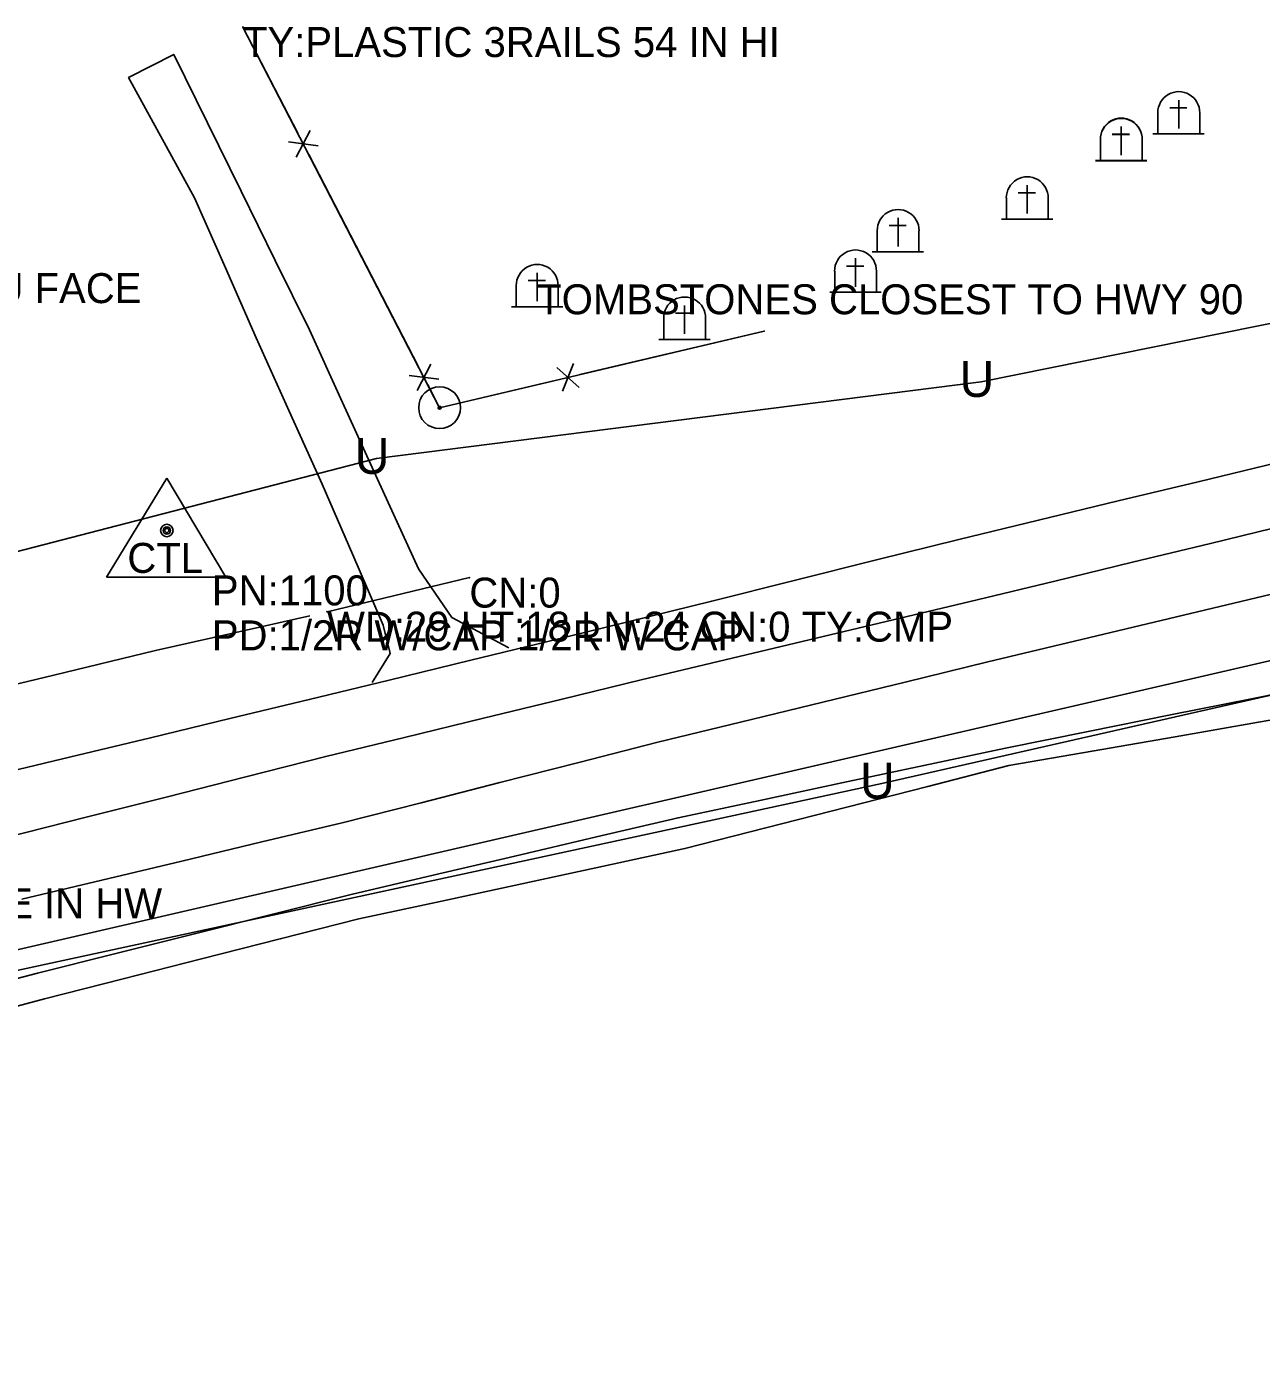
# Model space of a CAD drawing. Extents: x 1568433 to 1572450, y 731863 to 733450.
# Drawn here: x 1569410.1 to 1569616, y 731973.5 to 732195.3 of the extents above; entities that cross this region are included whole.
import ezdxf

# ---------------------------------------------------------------- set-up
doc = ezdxf.new("R2010")
doc.units = 0
for name, color, linetype in [('Default', 7, 'Continuous'), ('S_BASELINE', 7, 'Continuous'), ('S_BUILDING_ANNOT', 7, 'Continuous'), ('S_CROSS_DRAIN', 7, 'Continuous'), ('S_CROSS_DRAIN_ANNOT', 7, 'Continuous'), ('S_DITCHLINE', 7, 'Continuous'), ('S_DRG_PT_SYM', 7, 'Continuous'), ('S_DRIVEWAY', 7, 'Continuous'), ('S_EDGE_PAVEMENT', 7, 'Continuous'), ('S_FENCE', 7, 'Continuous'), ('S_FENCE_ANNOT', 7, 'Continuous'), ('S_MSC_PT_SYM', 7, 'Continuous'), ('S_PAVEMENT_CROWN', 7, 'Continuous'), ('S_PRIMARY_CTL', 7, 'Continuous'), ('S_PRIMARY_CTL_ANNOT', 7, 'Continuous'), ('S_TOMBSTONE', 7, 'Continuous'), ('S_TOMBSTONE_ANNOT', 7, 'Continuous'), ('S_UNDERGROUND_CABLE', 7, 'Continuous')]:
    doc.layers.add(name, color=color, linetype=linetype)

msp = doc.modelspace()

# ---------------------------------------------------------------- linework, layer by layer
at = {"layer": 'S_BASELINE'}
msp.add_line((1569114.63, 731973.54), (1569838.9, 732140.65), dxfattribs=at)
at = {"layer": 'S_CROSS_DRAIN'}
msp.add_line((1569460.2, 732097.74), (1569483.93, 732103.42), dxfattribs=at)
at = {"layer": 'S_DITCHLINE'}
for points in [[(1569330.52, 732066.86), (1569334.31, 732068.88), (1569357.83, 732073.3), (1569377.75, 732078.21), (1569397.67, 732083.12), (1569414.63, 732087.18), (1569431.6, 732091.25), (1569444.47, 732094.14), (1569457.35, 732097.03)], [(1569399.35, 732034.15), (1569411.9, 732037.47), (1569424.99, 732040.75), (1569438.07, 732044.04), (1569451.15, 732047.32), (1569464.24, 732050.6), (1569477.87, 732053.79), (1569491.49, 732056.99), (1569505.12, 732060.18), (1569518.75, 732063.37), (1569532.4, 732066.27), (1569546.05, 732069.17), (1569559.71, 732072.07), (1569573.36, 732074.96), (1569587.12, 732077.74), (1569600.88, 732080.51), (1569614.65, 732083.28), (1569628.41, 732086.06)], [(1569400.55, 732029.85), (1569413.06, 732033.17), (1569426.17, 732036.5), (1569439.27, 732039.83), (1569452.38, 732043.16), (1569465.48, 732046.49), (1569479.08, 732049.42), (1569492.68, 732052.35), (1569506.28, 732055.29), (1569519.87, 732058.22), (1569533.38, 732061.68), (1569546.89, 732065.14), (1569560.4, 732068.6), (1569573.91, 732072.06), (1569587.79, 732074.48), (1569601.67, 732076.89), (1569615.54, 732079.3), (1569629.42, 732081.72)]]:
    msp.add_lwpolyline(points, dxfattribs=at)
at = {"layer": 'S_DRG_PT_SYM'}
for points in [[(1569483.93, 732103.42), (1569483.93, 732103.47), (1569483.93, 732103.42), (1569483.88, 732103.42), (1569483.93, 732103.42), (1569483.93, 732103.37), (1569483.93, 732103.42), (1569483.98, 732103.42)], [(1569460.2, 732097.74), (1569460.2, 732097.79), (1569460.2, 732097.74), (1569460.15, 732097.74), (1569460.2, 732097.74), (1569460.2, 732097.69), (1569460.2, 732097.74), (1569460.25, 732097.74)]]:
    msp.add_lwpolyline(points, dxfattribs=at)
at = {"layer": 'S_DRIVEWAY'}
msp.add_lwpolyline([(1569467.73, 732085.91), (1569470.71, 732090.77), (1569469.58, 732095.49), (1569464.48, 732107.23), (1569459.38, 732118.98), (1569453.89, 732131.19), (1569448.4, 732143.4), (1569443.25, 732155.08), (1569438.1, 732166.76), (1569427.09, 732186.8), (1569434.63, 732190.68), (1569440.24, 732179.28), (1569445.85, 732167.88), (1569451.55, 732156.3), (1569457.25, 732144.72), (1569462.49, 732133.26), (1569467.72, 732121.8), (1569475.43, 732104.88), (1569481.03, 732096.75), (1569490.49, 732091.72)], dxfattribs=at)
at = {"layer": 'S_EDGE_PAVEMENT'}
for points in [[(1569404.23, 732070.38), (1569417.48, 732073.55), (1569430.73, 732076.72), (1569443.98, 732079.9), (1569457.24, 732083.07), (1569470.58, 732086.32), (1569483.93, 732089.58), (1569497.27, 732092.83), (1569510.61, 732096.08), (1569524.35, 732099.51), (1569538.09, 732102.93), (1569551.83, 732106.36), (1569565.57, 732109.79), (1569578.87, 732112.99), (1569592.17, 732116.2), (1569605.47, 732119.41), (1569618.77, 732122.62)], [(1569409.29, 732049.82), (1569422.64, 732052.99), (1569435.99, 732056.16), (1569449.34, 732059.34), (1569462.7, 732062.51), (1569475.87, 732065.88), (1569489.04, 732069.24), (1569502.21, 732072.61), (1569515.38, 732075.97), (1569529.13, 732079.31), (1569542.88, 732082.66), (1569556.63, 732086.01), (1569570.38, 732089.35), (1569583.67, 732092.52), (1569596.96, 732095.69), (1569610.25, 732098.87), (1569623.54, 732102.04)]]:
    msp.add_lwpolyline(points, dxfattribs=at)
at = {"layer": 'S_FENCE'}
for p, q in [((1569446.17, 732195.24), (1569478.97, 732131.76)), ((1569453.76, 732176.1), (1569458.71, 732175.44)), ((1569453.76, 732176.1), (1569458.71, 732175.44)), ((1569457.4, 732177.98), (1569455.07, 732173.56)), ((1569457.4, 732177.98), (1569455.07, 732173.56)), ((1569478.97, 732131.76), (1569533.09, 732144.52)), ((1569477.53, 732139.03), (1569475.2, 732134.61)), ((1569477.53, 732139.03), (1569475.2, 732134.61)), ((1569498.52, 732138.47), (1569502.25, 732135.14)), ((1569498.52, 732138.47), (1569502.25, 732135.14)), ((1569499.46, 732134.49), (1569501.31, 732139.13)), ((1569499.46, 732134.49), (1569501.31, 732139.13)), ((1569473.89, 732137.15), (1569478.84, 732136.49)), ((1569473.89, 732137.15), (1569478.84, 732136.49))]:
    msp.add_line(p, q, dxfattribs=at)
for points in [[(1569446.17, 732195.24), (1569455.32, 732177.54)], [(1569446.17, 732195.24), (1569455.32, 732177.54)], [(1569457.15, 732174), (1569475.45, 732138.59)], [(1569457.15, 732174), (1569475.45, 732138.59)], [(1569502.33, 732137.27), (1569533.09, 732144.52)], [(1569502.33, 732137.27), (1569533.09, 732144.52)], [(1569478.97, 732131.76), (1569498.44, 732136.35)], [(1569478.97, 732131.76), (1569498.44, 732136.35)], [(1569477.02, 732135.55), (1569478.97, 732131.76)], [(1569477.02, 732135.55), (1569478.97, 732131.76)]]:
    msp.add_lwpolyline(points, dxfattribs=at)
for radius in [3.49, 0.247, 0.0349]:
    msp.add_circle((1569478.97, 732131.76), radius, dxfattribs=at)
at = {"layer": 'S_MSC_PT_SYM'}
for points in [[(1569446.17, 732195.24), (1569446.17, 732195.29), (1569446.17, 732195.24), (1569446.12, 732195.24), (1569446.17, 732195.24), (1569446.17, 732195.19), (1569446.17, 732195.24), (1569446.22, 732195.24)], [(1569533.09, 732144.52), (1569533.09, 732144.57), (1569533.09, 732144.52), (1569533.04, 732144.52), (1569533.09, 732144.52), (1569533.09, 732144.47), (1569533.09, 732144.52), (1569533.14, 732144.52)], [(1569478.97, 732131.76), (1569478.97, 732131.81), (1569478.97, 732131.76), (1569478.92, 732131.76), (1569478.97, 732131.76), (1569478.97, 732131.71), (1569478.97, 732131.76), (1569479.02, 732131.76)]]:
    msp.add_lwpolyline(points, dxfattribs=at)
at = {"layer": 'S_PAVEMENT_CROWN'}
msp.add_lwpolyline([(1569406.7, 732060.07), (1569420.02, 732063.45), (1569433.34, 732066.83), (1569446.66, 732070.21), (1569459.98, 732073.59), (1569473.13, 732076.78), (1569486.27, 732079.97), (1569499.41, 732083.16), (1569512.56, 732086.35), (1569526.57, 732089.69), (1569540.59, 732093.02), (1569554.6, 732096.36), (1569568.61, 732099.7), (1569581.58, 732102.84), (1569594.55, 732105.98), (1569607.52, 732109.12), (1569620.49, 732112.26)], dxfattribs=at)
at = {"layer": 'S_PRIMARY_CTL'}
for p, q in [((1569433.48, 732119.99), (1569423.44, 732103.47)), ((1569433.48, 732119.99), (1569423.44, 732103.47)), ((1569433.48, 732119.99), (1569443.3, 732103.47)), ((1569433.48, 732119.99), (1569443.3, 732103.47)), ((1569423.44, 732103.47), (1569443.3, 732103.47)), ((1569423.44, 732103.47), (1569443.3, 732103.47))]:
    msp.add_line(p, q, dxfattribs=at)
for radius in [1.04, 1.04, 0.609, 0.609, 0.344, 0.344]:
    msp.add_circle((1569433.48, 732111.29), radius, dxfattribs=at)
at = {"layer": 'S_TOMBSTONE'}
for p, q in [((1569602.25, 732183.07), (1569602.25, 732178.34)), ((1569598.76, 732180.94), (1569598.76, 732177.41)), ((1569600.74, 732181.79), (1569603.61, 732181.79)), ((1569605.74, 732180.94), (1569605.74, 732177.49)), ((1569592.66, 732178.65), (1569592.66, 732173.92)), ((1569592.67, 732178.61), (1569592.67, 732173.88)), ((1569589.17, 732176.52), (1569589.17, 732172.99)), ((1569589.18, 732176.47), (1569589.18, 732172.95)), ((1569591.15, 732177.37), (1569594.02, 732177.37)), ((1569591.16, 732177.33), (1569594.03, 732177.33)), ((1569596.15, 732176.52), (1569596.15, 732173.07)), ((1569596.16, 732176.47), (1569596.16, 732173.03)), ((1569597.95, 732177.41), (1569606.51, 732177.41)), ((1569588.36, 732172.99), (1569596.92, 732172.99)), ((1569588.37, 732172.95), (1569596.93, 732172.95)), ((1569575.47, 732167.59), (1569578.34, 732167.59)), ((1569576.98, 732168.87), (1569576.98, 732164.14)), ((1569573.5, 732166.74), (1569573.5, 732163.21)), ((1569580.47, 732166.74), (1569580.47, 732163.29)), ((1569555.44, 732163.4), (1569555.44, 732158.67)), ((1569572.68, 732163.21), (1569581.25, 732163.21)), ((1569551.95, 732161.27), (1569551.95, 732157.74)), ((1569553.93, 732162.12), (1569556.79, 732162.12)), ((1569558.92, 732161.27), (1569558.92, 732157.82)), ((1569548.34, 732156.67), (1569548.34, 732151.94)), ((1569551.14, 732157.74), (1569559.7, 732157.74)), ((1569495.25, 732154.26), (1569495.25, 732149.53)), ((1569544.86, 732154.54), (1569544.86, 732151.01)), ((1569546.83, 732155.39), (1569549.7, 732155.39)), ((1569551.83, 732154.54), (1569551.83, 732151.09)), ((1569491.76, 732152.13), (1569491.76, 732148.6)), ((1569493.74, 732152.98), (1569496.61, 732152.98)), ((1569498.74, 732152.13), (1569498.74, 732148.68)), ((1569544.04, 732151.01), (1569552.61, 732151.01)), ((1569490.95, 732148.6), (1569499.51, 732148.6)), ((1569518.33, 732147.54), (1569521.2, 732147.54)), ((1569519.84, 732148.82), (1569519.84, 732144.09)), ((1569516.35, 732146.69), (1569516.35, 732143.16)), ((1569523.33, 732146.69), (1569523.33, 732143.24)), ((1569515.54, 732143.16), (1569524.1, 732143.16))]:
    msp.add_line(p, q, dxfattribs=at)
for centre in [(1569602.25, 732180.98), (1569592.66, 732176.56), (1569592.67, 732176.51), (1569576.98, 732166.78), (1569555.44, 732161.31), (1569548.34, 732154.57), (1569495.25, 732152.16), (1569519.84, 732146.73)]:
    msp.add_arc(centre, 3.49, 359.3489, 180.6228, dxfattribs=at)
at = {"layer": 'S_UNDERGROUND_CABLE'}
for p, q in [((1569569.32, 732136.1), (1569634.25, 732149.16)), ((1569468.44, 732123.27), (1569569.32, 732136.1)), ((1569332.4, 732088.07), (1569468.44, 732123.27)), ((1569641.2, 732089.16), (1569552.71, 732069.09)), ((1569552.71, 732069.09), (1569253.35, 732004.42))]:
    msp.add_line(p, q, dxfattribs=at)

# ---------------------------------------------------------------- texts
at = {"layer": 'Default'}
for p in [(1569565.69, 732133.55), (1569464.81, 732120.73), (1569549.08, 732066.55)]:
    msp.add_text('U', height=6, dxfattribs=at).set_placement(p)
at = {"layer": 'S_BUILDING_ANNOT'}
msp.add_text('11.0 FT TO BU FACE', height=5, dxfattribs=at).set_placement((1569364.23, 732149.2))
at = {"layer": 'S_CROSS_DRAIN_ANNOT'}
for s, p in [('CN:0', (1569483.93, 732098.42)), ('WD:29 HT:18 LN:24 CN:0 TY:CMP', (1569460.2, 732092.74))]:
    msp.add_text(s, height=5, dxfattribs=at).set_placement(p)
at = {"layer": 'S_FENCE_ANNOT'}
msp.add_text('TY:PLASTIC 3RAILS 54 IN HI', height=5, dxfattribs=at).set_placement((1569446.17, 732190.24))
at = {"layer": 'S_PRIMARY_CTL'}
msp.add_text('CTL', height=5, rotation=360, dxfattribs=at).set_placement((1569426.89, 732104.21))
msp.add_text('CTL', height=5, dxfattribs=at).set_placement((1569426.89, 732104.21))
at = {"layer": 'S_PRIMARY_CTL_ANNOT'}
for s, p in [('PN:1100', (1569440.98, 732098.79)), ('PD:1/2R W/CAP 1/2R W CAP', (1569440.98, 732091.29)), ('PD:CHISELED SQUARE IN HW', (1569336.46, 732046.58))]:
    msp.add_text(s, height=5, dxfattribs=at).set_placement(p)
at = {"layer": 'S_TOMBSTONE_ANNOT'}
msp.add_text('TOMBSTONES CLOSEST TO HWY 90', height=5, dxfattribs=at).set_placement((1569495.25, 732147.34))

doc.saveas('drawing.dxf')
